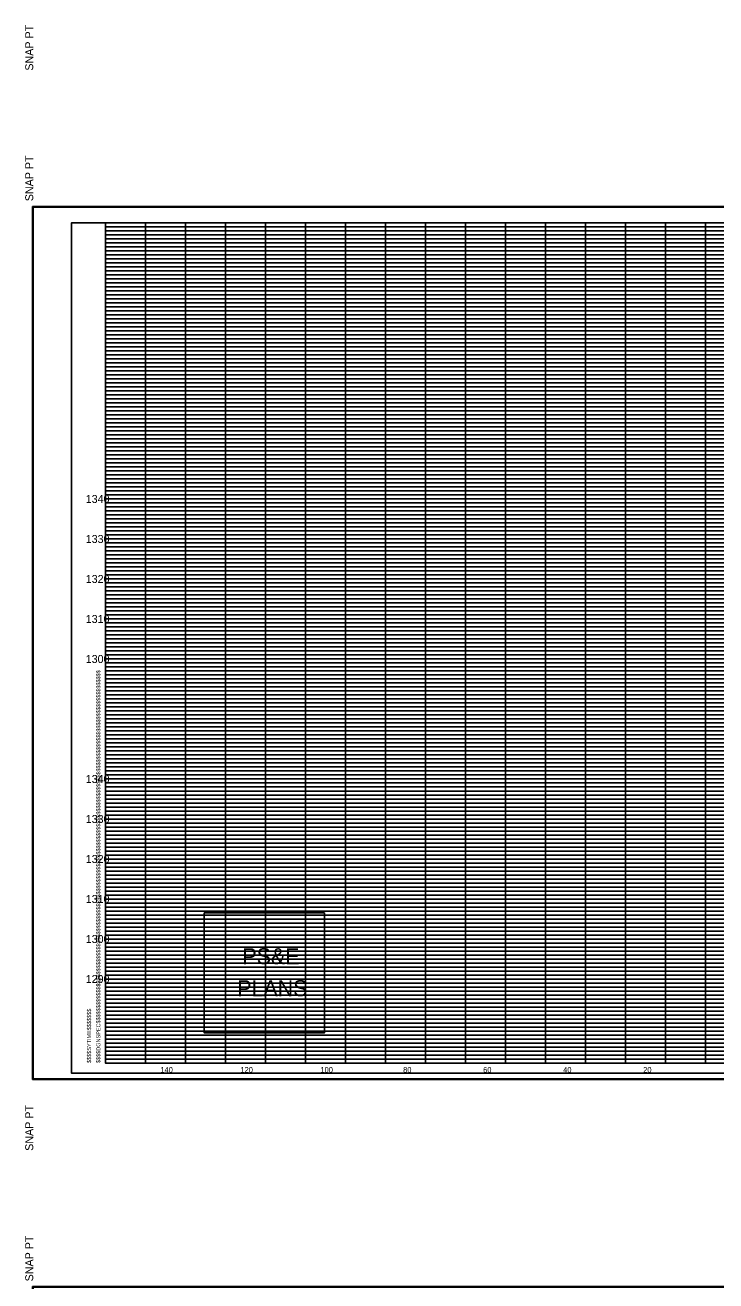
# Model space of a CAD drawing. Extents: x 980 to 1324, y 978 to 2847.
# Drawn here: x 979.9 to 1152.6, y 1485.5 to 1799.4 of the extents above; entities that cross this region are included whole.
import ezdxf

# ---------------------------------------------------------------- set-up
doc = ezdxf.new("R2010")
doc.units = 0
for name, color, linetype in [('DESIGN - SHEET - Corner Text', 7, 'Continuous'), ('DESIGN - SHEET - Light Grid', 7, 'Continuous'), ('DESIGN - SHEET - Linework', 7, 'Continuous'), ('DESIGN - SHEET - Plot Shape', 7, 'Continuous'), ('DESIGN - TYPICAL - Text', 7, 'Continuous')]:
    doc.layers.add(name, color=color, linetype=linetype)

# ---------------------------------------------------------------- blocks, each defined once
blk = doc.blocks.new('XSTSHT')
at = {"layer": 'DESIGN - SHEET - Light Grid'}
for p, q in [((0, 20.9), (8, 20.9)), ((0, 20.8), (8, 20.8)), ((8, 20.9), (16, 20.9)), ((8, 20.8), (16, 20.8)), ((0, 20.7), (8, 20.7)), ((0, 20.6), (8, 20.6)), ((0, 20.5), (8, 20.5)), ((8, 20.7), (16, 20.7)), ((8, 20.6), (16, 20.6)), ((8, 20.5), (16, 20.5)), ((0, 20.4), (8, 20.4)), ((0, 20.3), (8, 20.3)), ((0, 20.2), (8, 20.2)), ((0, 20.1), (8, 20.1)), ((8, 20.4), (16, 20.4)), ((8, 20.3), (16, 20.3)), ((8, 20.2), (16, 20.2)), ((8, 20.1), (16, 20.1)), ((0, 19.9), (8, 19.9)), ((0, 19.8), (8, 19.8)), ((8, 19.9), (16, 19.9)), ((8, 19.8), (16, 19.8)), ((0, 19.7), (8, 19.7)), ((0, 19.6), (8, 19.6)), ((0, 19.5), (8, 19.5)), ((8, 19.7), (16, 19.7)), ((8, 19.6), (16, 19.6)), ((8, 19.5), (16, 19.5)), ((0, 19.4), (8, 19.4)), ((0, 19.3), (8, 19.3)), ((0, 19.2), (8, 19.2)), ((8, 19.4), (16, 19.4)), ((8, 19.3), (16, 19.3)), ((8, 19.2), (16, 19.2)), ((0, 19.1), (8, 19.1)), ((0, 18.9), (8, 18.9)), ((8, 19.1), (16, 19.1)), ((8, 18.9), (16, 18.9)), ((0, 18.8), (8, 18.8)), ((0, 18.7), (8, 18.7)), ((0, 18.6), (8, 18.6)), ((8, 18.8), (16, 18.8)), ((8, 18.7), (16, 18.7)), ((8, 18.6), (16, 18.6)), ((0, 18.5), (8, 18.5)), ((0, 18.4), (8, 18.4)), ((0, 18.3), (8, 18.3)), ((8, 18.5), (16, 18.5)), ((8, 18.4), (16, 18.4)), ((8, 18.3), (16, 18.3)), ((0, 18.2), (8, 18.2)), ((0, 18.1), (8, 18.1)), ((0, 17.9), (8, 17.9)), ((8, 18.2), (16, 18.2)), ((8, 18.1), (16, 18.1)), ((8, 17.9), (16, 17.9)), ((0, 17.8), (8, 17.8)), ((0, 17.7), (8, 17.7)), ((0, 17.6), (8, 17.6)), ((8, 17.8), (16, 17.8)), ((8, 17.7), (16, 17.7)), ((8, 17.6), (16, 17.6)), ((0, 17.5), (8, 17.5)), ((0, 17.4), (8, 17.4)), ((0, 17.3), (8, 17.3)), ((8, 17.5), (16, 17.5)), ((8, 17.4), (16, 17.4)), ((8, 17.3), (16, 17.3)), ((0, 17.2), (8, 17.2)), ((0, 17.1), (8, 17.1)), ((8, 17.2), (16, 17.2)), ((8, 17.1), (16, 17.1)), ((0, 16.9), (8, 16.9)), ((0, 16.8), (8, 16.8)), ((0, 16.7), (8, 16.7)), ((8, 16.9), (16, 16.9)), ((8, 16.8), (16, 16.8)), ((8, 16.7), (16, 16.7)), ((0, 16.6), (8, 16.6)), ((0, 16.5), (8, 16.5)), ((0, 16.4), (8, 16.4)), ((8, 16.6), (16, 16.6)), ((8, 16.5), (16, 16.5)), ((8, 16.4), (16, 16.4)), ((0, 16.3), (8, 16.3)), ((0, 16.2), (8, 16.2)), ((0, 16.1), (8, 16.1)), ((8, 16.3), (16, 16.3)), ((8, 16.2), (16, 16.2)), ((8, 16.1), (16, 16.1)), ((0, 15.9), (8, 15.9)), ((0, 15.8), (8, 15.8)), ((0, 15.7), (8, 15.7)), ((8, 15.9), (16, 15.9)), ((8, 15.8), (16, 15.8)), ((8, 15.7), (16, 15.7)), ((0, 15.6), (8, 15.6)), ((0, 15.5), (8, 15.5)), ((0, 15.4), (8, 15.4)), ((8, 15.6), (16, 15.6)), ((8, 15.5), (16, 15.5)), ((8, 15.4), (16, 15.4)), ((0, 15.3), (8, 15.3)), ((0, 15.2), (8, 15.2)), ((0, 15.1), (8, 15.1)), ((8, 15.3), (16, 15.3)), ((8, 15.2), (16, 15.2)), ((8, 15.1), (16, 15.1)), ((0, 14.9), (8, 14.9)), ((0, 14.8), (8, 14.8)), ((8, 14.9), (16, 14.9)), ((8, 14.8), (16, 14.8)), ((0, 14.7), (8, 14.7)), ((0, 14.6), (8, 14.6)), ((0, 14.5), (8, 14.5)), ((8, 14.7), (16, 14.7)), ((8, 14.6), (16, 14.6)), ((8, 14.5), (16, 14.5)), ((0, 14.4), (8, 14.4)), ((0, 14.3), (8, 14.3)), ((0, 14.2), (8, 14.2)), ((8, 14.4), (16, 14.4)), ((8, 14.3), (16, 14.3)), ((8, 14.2), (16, 14.2)), ((0, 14.1), (8, 14.1)), ((0, 13.9), (8, 13.9)), ((8, 14.1), (16, 14.1)), ((8, 13.9), (16, 13.9)), ((0, 13.8), (8, 13.8)), ((0, 13.7), (8, 13.7)), ((0, 13.6), (8, 13.6)), ((0, 13.5), (8, 13.5)), ((8, 13.8), (16, 13.8)), ((8, 13.7), (16, 13.7)), ((8, 13.6), (16, 13.6)), ((8, 13.5), (16, 13.5)), ((0, 13.4), (8, 13.4)), ((0, 13.3), (8, 13.3)), ((0, 13.2), (8, 13.2)), ((8, 13.4), (16, 13.4)), ((8, 13.3), (16, 13.3)), ((8, 13.2), (16, 13.2)), ((0, 13.1), (8, 13.1)), ((0, 12.9), (8, 12.9)), ((8, 13.1), (16, 13.1)), ((8, 12.9), (16, 12.9)), ((0, 12.8), (8, 12.8)), ((0, 12.7), (8, 12.7)), ((0, 12.6), (8, 12.6)), ((8, 12.8), (16, 12.8)), ((8, 12.7), (16, 12.7)), ((8, 12.6), (16, 12.6)), ((0, 12.5), (8, 12.5)), ((0, 12.4), (8, 12.4)), ((0, 12.3), (8, 12.3)), ((8, 12.5), (16, 12.5)), ((8, 12.4), (16, 12.4)), ((8, 12.3), (16, 12.3)), ((0, 12.2), (8, 12.2)), ((0, 12.1), (8, 12.1)), ((8, 12.2), (16, 12.2)), ((8, 12.1), (16, 12.1)), ((0, 11.9), (8, 11.9)), ((0, 11.8), (8, 11.8)), ((0, 11.7), (8, 11.7)), ((8, 11.9), (16, 11.9)), ((8, 11.8), (16, 11.8)), ((8, 11.7), (16, 11.7)), ((0, 11.6), (8, 11.6)), ((0, 11.5), (8, 11.5)), ((0, 11.4), (8, 11.4)), ((8, 11.6), (16, 11.6)), ((8, 11.5), (16, 11.5)), ((8, 11.4), (16, 11.4)), ((0, 11.3), (8, 11.3)), ((0, 11.2), (8, 11.2)), ((0, 11.1), (8, 11.1)), ((8, 11.3), (16, 11.3)), ((8, 11.2), (16, 11.2)), ((8, 11.1), (16, 11.1)), ((0, 10.9), (8, 10.9)), ((0, 10.8), (8, 10.8)), ((0, 10.7), (8, 10.7)), ((8, 10.9), (16, 10.9)), ((8, 10.8), (16, 10.8)), ((8, 10.7), (16, 10.7)), ((0, 10.6), (8, 10.6)), ((0, 10.5), (8, 10.5)), ((0, 10.4), (8, 10.4)), ((8, 10.6), (16, 10.6)), ((8, 10.5), (16, 10.5)), ((8, 10.4), (16, 10.4)), ((0, 10.3), (8, 10.3)), ((0, 10.2), (8, 10.2)), ((0, 10.1), (8, 10.1)), ((8, 10.3), (16, 10.3)), ((8, 10.2), (16, 10.2)), ((8, 10.1), (16, 10.1)), ((0, 9.9), (8, 9.9)), ((0, 9.8), (8, 9.8)), ((8, 9.9), (16, 9.9)), ((8, 9.8), (16, 9.8)), ((0, 9.7), (8, 9.7)), ((0, 9.6), (8, 9.6)), ((0, 9.5), (8, 9.5)), ((8, 9.7), (16, 9.7)), ((8, 9.6), (16, 9.6)), ((8, 9.5), (16, 9.5)), ((0, 9.4), (8, 9.4)), ((0, 9.3), (8, 9.3)), ((0, 9.2), (8, 9.2)), ((8, 9.4), (16, 9.4)), ((8, 9.3), (16, 9.3)), ((8, 9.2), (16, 9.2)), ((0, 9.1), (8, 9.1)), ((0, 8.9), (8, 8.9)), ((0, 8.8), (8, 8.8)), ((8, 9.1), (16, 9.1)), ((8, 8.9), (16, 8.9)), ((8, 8.8), (16, 8.8)), ((0, 8.7), (8, 8.7)), ((0, 8.6), (8, 8.6)), ((0, 8.5), (8, 8.5)), ((8, 8.7), (16, 8.7)), ((8, 8.6), (16, 8.6)), ((8, 8.5), (16, 8.5)), ((0, 8.4), (8, 8.4)), ((0, 8.3), (8, 8.3)), ((0, 8.2), (8, 8.2)), ((8, 8.4), (16, 8.4)), ((8, 8.3), (16, 8.3)), ((8, 8.2), (16, 8.2)), ((0, 8.1), (8, 8.1)), ((0, 7.9), (8, 7.9)), ((8, 8.1), (16, 8.1)), ((8, 7.9), (16, 7.9)), ((0, 7.8), (8, 7.8)), ((0, 7.7), (8, 7.7)), ((0, 7.6), (8, 7.6)), ((8, 7.8), (16, 7.8)), ((8, 7.7), (16, 7.7)), ((8, 7.6), (16, 7.6)), ((0, 7.5), (8, 7.5)), ((0, 7.4), (8, 7.4)), ((0, 7.3), (8, 7.3)), ((8, 7.5), (16, 7.5)), ((8, 7.4), (16, 7.4)), ((8, 7.3), (16, 7.3)), ((0, 7.2), (8, 7.2)), ((0, 7.1), (8, 7.1)), ((8, 7.2), (16, 7.2)), ((8, 7.1), (16, 7.1)), ((0, 6.9), (8, 6.9)), ((0, 6.8), (8, 6.8)), ((0, 6.7), (8, 6.7)), ((0, 6.6), (8, 6.6)), ((8, 6.9), (16, 6.9)), ((8, 6.8), (16, 6.8)), ((8, 6.7), (16, 6.7)), ((8, 6.6), (16, 6.6)), ((0, 6.5), (8, 6.5)), ((0, 6.4), (8, 6.4)), ((0, 6.3), (8, 6.3)), ((8, 6.5), (16, 6.5)), ((8, 6.4), (16, 6.4)), ((8, 6.3), (16, 6.3)), ((0, 6.2), (8, 6.2)), ((0, 6.1), (8, 6.1)), ((8, 6.2), (16, 6.2)), ((8, 6.1), (16, 6.1)), ((0, 5.9), (8, 5.9)), ((0, 5.8), (8, 5.8)), ((0, 5.7), (8, 5.7)), ((8, 5.9), (16, 5.9)), ((8, 5.8), (16, 5.8)), ((8, 5.7), (16, 5.7)), ((0, 5.6), (8, 5.6)), ((0, 5.5), (8, 5.5)), ((0, 5.4), (8, 5.4)), ((8, 5.6), (16, 5.6)), ((8, 5.5), (16, 5.5)), ((8, 5.4), (16, 5.4)), ((0, 5.3), (8, 5.3)), ((0, 5.2), (8, 5.2)), ((0, 5.1), (8, 5.1)), ((8, 5.3), (16, 5.3)), ((8, 5.2), (16, 5.2)), ((8, 5.1), (16, 5.1)), ((0, 4.9), (8, 4.9)), ((0, 4.8), (8, 4.8)), ((8, 4.9), (16, 4.9)), ((8, 4.8), (16, 4.8)), ((0, 4.7), (8, 4.7)), ((0, 4.6), (8, 4.6)), ((0, 4.5), (8, 4.5)), ((0, 4.4), (8, 4.4)), ((8, 4.7), (16, 4.7)), ((8, 4.6), (16, 4.6)), ((8, 4.5), (16, 4.5)), ((8, 4.4), (16, 4.4)), ((0, 4.3), (8, 4.3)), ((0, 4.2), (8, 4.2)), ((0, 4.1), (8, 4.1)), ((8, 4.3), (16, 4.3)), ((8, 4.2), (16, 4.2)), ((8, 4.1), (16, 4.1)), ((0, 3.9), (8, 3.9)), ((0, 3.8), (8, 3.8)), ((8, 3.9), (16, 3.9)), ((8, 3.8), (16, 3.8)), ((0, 3.7), (8, 3.7)), ((0, 3.6), (8, 3.6)), ((0, 3.5), (8, 3.5)), ((8, 3.7), (16, 3.7)), ((8, 3.6), (16, 3.6)), ((8, 3.5), (16, 3.5)), ((0, 3.4), (8, 3.4)), ((0, 3.3), (8, 3.3)), ((0, 3.2), (8, 3.2)), ((8, 3.4), (16, 3.4)), ((8, 3.3), (16, 3.3)), ((8, 3.2), (16, 3.2)), ((0, 3.1), (8, 3.1)), ((0, 2.9), (8, 2.9)), ((8, 3.1), (16, 3.1)), ((8, 2.9), (16, 2.9)), ((0, 2.8), (8, 2.8)), ((0, 2.7), (8, 2.7)), ((0, 2.6), (8, 2.6)), ((8, 2.8), (16, 2.8)), ((8, 2.7), (16, 2.7)), ((8, 2.6), (16, 2.6)), ((0, 2.5), (8, 2.5)), ((0, 2.4), (8, 2.4)), ((0, 2.3), (8, 2.3)), ((0, 2.2), (8, 2.2)), ((8, 2.5), (16, 2.5)), ((8, 2.4), (16, 2.4)), ((8, 2.3), (16, 2.3)), ((8, 2.2), (16, 2.2)), ((0, 2.1), (8, 2.1)), ((0, 1.9), (8, 1.9)), ((8, 2.1), (16, 2.1)), ((8, 1.9), (16, 1.9)), ((0, 1.8), (8, 1.8)), ((0, 1.7), (8, 1.7)), ((0, 1.6), (8, 1.6)), ((8, 1.8), (16, 1.8)), ((8, 1.7), (16, 1.7)), ((8, 1.6), (16, 1.6)), ((0, 1.5), (8, 1.5)), ((0, 1.4), (8, 1.4)), ((0, 1.3), (8, 1.3)), ((8, 1.5), (16, 1.5)), ((8, 1.4), (16, 1.4)), ((8, 1.3), (16, 1.3)), ((0, 1.2), (8, 1.2)), ((0, 1.1), (8, 1.1)), ((8, 1.2), (16, 1.2)), ((8, 1.1), (16, 1.1)), ((0, 0.9), (8, 0.9)), ((0, 0.8), (8, 0.8)), ((0, 0.7), (8, 0.7)), ((8, 0.9), (16, 0.9)), ((8, 0.8), (16, 0.8)), ((8, 0.7), (16, 0.7)), ((0, 0.6), (8, 0.6)), ((0, 0.5), (8, 0.5)), ((0, 0.4), (8, 0.4)), ((8, 0.6), (16, 0.6)), ((8, 0.5), (16, 0.5)), ((8, 0.4), (16, 0.4)), ((0, 0.3), (8, 0.3)), ((0, 0.2), (8, 0.2)), ((0, 0.1), (8, 0.1)), ((8, 0.3), (16, 0.3)), ((8, 0.2), (16, 0.2)), ((8, 0.1), (16, 0.1))]:
    blk.add_line(p, q, dxfattribs=at)
at = {"layer": 'DESIGN - SHEET - Linework'}
for p, q in [((-1.823, -0.414), (-1.823, 21.414)), ((-1.823, 21.414), (32.217, 21.414)), ((1, 0), (1, 21)), ((2, 0), (2, 21)), ((3, 0), (3, 21)), ((4, 0), (4, 21)), ((5, 0), (5, 21)), ((6, 0), (6, 21)), ((7, 0), (7, 21)), ((8, 0), (8, 21)), ((9, 0), (9, 21)), ((10, 0), (10, 21)), ((11, 0), (11, 21)), ((12, 0), (12, 21)), ((13, 0), (13, 21)), ((14, 0), (14, 21)), ((15, 0), (15, 21)), ((0, 20), (28, 20)), ((0, 19), (32, 19)), ((0, 18), (32, 18)), ((0, 17), (32, 17)), ((0, 16), (32, 16)), ((0, 15), (32, 15)), ((0, 14), (32, 14)), ((0, 13), (32, 13)), ((0, 12), (32, 12)), ((0, 11), (32, 11)), ((0, 10), (32, 10)), ((0, 9), (32, 9)), ((0, 8), (32, 8)), ((0, 7), (32, 7)), ((0, 6), (32, 6)), ((0, 5), (32, 5)), ((0, 4), (32, 4)), ((0, 3), (32, 3)), ((0, 2), (32, 2)), ((0, 1), (32, 1)), ((-1.823, -0.414), (32.217, -0.414))]:
    blk.add_line(p, q, dxfattribs=at)
blk.add_lwpolyline([(0, 21), (0, 0), (32, 0), (32, 21), (0, 21)], dxfattribs=at)
at = {"layer": 'DESIGN - SHEET - Plot Shape'}
for points in [[(-1.803, 21.394), (32.197, 21.394), (32.197, -0.394), (-1.803, -0.394)], [(-0.85, 21), (32, 21), (32, -0.25), (-0.85, -0.25)]]:
    blk.add_lwpolyline(points, close=True, dxfattribs=at)
at = {"layer": 'DESIGN - SHEET - Corner Text'}
for s, height, p in [('  SNAP PT', 0.2, (-1.803, 21.394)), ('$$$$DGNSPEC$$$$$$$$$$$$$$$$$$$$$$$$$$$$$$$$$$$$$$$$$$$$$$$$$$$$$$$$$$$$$$$$$$$$$$$$$$$$$$$$$$$$$$$$$$$$$$$$$$$$$$$$$$$$$$$$$$$', 0.100002, (-0.126, 0)), ('$$$$SYTIME$$$$$$$', 0.1, (-0.358, 0)), ('SNAP PT  ', 0.2, (-1.803, -2.194))]:
    blk.add_text(s, height=height, rotation=90, dxfattribs=at).set_placement(p)

msp = doc.modelspace()

# ---------------------------------------------------------------- linework, layer by layer
at = {"layer": 'DESIGN - SHEET - Corner Text'}
msp.add_lwpolyline([(1024.73, 1577.53), (1024.73, 1547.53), (1054.73, 1547.53), (1054.73, 1577.53)], close=True, dxfattribs=at)
at = {"layer": 'DESIGN - SHEET - Plot Shape'}
msp.add_lwpolyline([(991.5, 1537.5), (1320, 1537.5), (1320, 1750), (991.5, 1750)], close=True, dxfattribs=at)

# ---------------------------------------------------------------- block references
at = {"layer": 'DESIGN - SHEET - Plot Shape', "xscale": 10, "yscale": 10}
for p in [(1000, 1810), (1000, 1540), (1000, 1270)]:
    msp.add_blockref('XSTSHT', p, dxfattribs=at)

# ---------------------------------------------------------------- texts
at = {"layer": 'DESIGN - SHEET - Corner Text'}
for s, p in [('PS&E', (1034.25, 1564.71)), ('PLANS', (1032.96, 1556.71))]:
    msp.add_text(s, height=4, dxfattribs=at).set_placement(p)
at = {"layer": 'DESIGN - TYPICAL - Text'}
for s, height, p in [('     1340     ', 2, (991.37, 1680)), ('     1330     ', 2, (991.37, 1670)), ('     1320     ', 2, (991.37, 1660)), ('     1310     ', 2, (991.37, 1650)), ('     1300     ', 2, (991.37, 1640)), ('     1340     ', 2, (991.37, 1610)), ('     1330     ', 2, (991.37, 1600)), ('     1320     ', 2, (991.37, 1590)), ('     1310     ', 2, (991.37, 1580)), ('     1300     ', 2, (991.37, 1570)), ('     1290     ', 2, (991.37, 1560)), ('     140     ', 1.4, (1011.14, 1537.6)), ('     120     ', 1.4, (1031.14, 1537.6)), ('     100     ', 1.4, (1051.14, 1537.6)), ('     80     ', 1.4, (1071.82, 1537.6)), ('     60     ', 1.4, (1091.82, 1537.6)), ('     40     ', 1.4, (1111.82, 1537.6)), ('     20     ', 1.4, (1131.82, 1537.6))]:
    msp.add_text(s, height=height, dxfattribs=at).set_placement(p)

doc.saveas('drawing.dxf')
